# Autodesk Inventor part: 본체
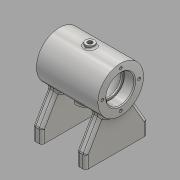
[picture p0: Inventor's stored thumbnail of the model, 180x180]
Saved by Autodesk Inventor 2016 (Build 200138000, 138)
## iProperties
Created: 2018-05
Part Number: 본체
Material: 알루미늄 6061
Document SubType Name: Modeling
Designer: Administrator
Density: 2.7 g/cm^3
Appearance: 알루미늄 - 평지
Mass: 317.695 g
Surface Area: 375.824 cm^2
Volume: 117.665 cm^3
Author: Administrator
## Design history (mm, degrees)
sketch "스케치1"
  geometry: L1 (-20, -35)-(-30, -35); L2 (-30, -35)-(-30, 35); L3 (-30, 35)-(-20, 35); L4 (-20, 35)-(-20, -35); L5 (-42, 0)-(42, 0) reference; L6 (0, -49)-(0, 49) reference; L7 (20, -35)-(30, -35); L8 (30, -35)-(30, 35); L9 (30, 35)-(20, 35); L10 (20, 35)-(20, -35); 1 further point
  constraints: 16 end point, 4 parallel, 2 horizontal, 2 perpendicular, 5 other
  dimensions: "d0" = 10 distance of L2.end L3.end; "d1" = 60 distance between parallel lines of L2 L8; "d2" = 70 distance of L9.end L7.start
extrude "돌출1" new body sketch "스케치1" distance "d3" = 15; taper "d4" = 0 deg
sketch "스케치2"
  geometry: L1 (36.295, 65)-(-44.666, 65); L2 (35, 65)-(-35, 65); L3 (-35, 65)-(-35, 91); L4 (-35, 91)-(35, 91); L5 (35, 91)-(35, 65); L6 (35, 65)-(23, 65); L7 (23, 65)-(23, 81); L8 (23, 81)-(35, 81); L9 (35, 81)-(35, 65); L10 (23, 65)-(21, 65); L11 (21, 65)-(21, 79); L12 (21, 79)-(23, 79); L13 (23, 79)-(23, 65); L14 (21, 65)-(-21, 65); L15 (-21, 65)-(-21, 86); L16 (-21, 86)-(21, 86); L17 (21, 86)-(21, 65); L18 (-21, 65)-(-23, 65); L19 (-23, 65)-(-23, 79); L20 (-23, 79)-(-21, 79); L21 (-21, 79)-(-21, 65); L22 (-23, 65)-(-35, 65); L23 (-35, 65)-(-35, 81); L24 (-35, 81)-(-23, 81); L25 (-23, 81)-(-23, 65); 2 further points
  constraints: 50 end point, 12 parallel, 7 horizontal, 6 perpendicular, 1 midpoint, 1 point on line, 1 vertical alignment
  dimensions: "d5" = 65 distance from line of point (0, 0) L1; "d6" = 70 distance of L3.end L4.end; "d7" = 26 distance of L2.end L3.end; "d8" = 12 distance of L7.end L8.end; "d9" = 16 distance of L6.end L7.end; "d10" = 2 distance of L11.end L12.end; "d11" = 14 distance of L10.end L11.end; "d12" = 42 distance of L15.end L16.end; "d13" = 21 distance of L14.end L15.end; "d14" = 2 distance of L19.end L20.end; "d15" = 14 distance of L18.end L19.end; "d16" = 12 distance of L23.end L24.end; "d17" = 16 distance of L22.end L23.end
revolve "회전1" sketch "스케치2" stored, may be unused: angle "d18" = 90 deg
sketch "스케치3"
  geometry: L1 (-30, -35)-(-30, 35) reference; L2 (-20, 35)-(-20, -35) reference; L3 (-30, -3)-(-20, -3); L4 (-20, -3)-(-20, 3); L5 (-20, 3)-(-30, 3); L6 (-30, 3)-(-30, -3); L7 (30, -35)-(30, 35) reference; L8 (20, 35)-(20, -35) reference; L9 (30, -3)-(20, -3); L10 (20, -3)-(20, 3); L11 (20, 3)-(30, 3); L12 (30, 3)-(30, -3); 4 further points
  constraints: 16 end point, 4 parallel, 4 point on line, 3 horizontal alignment, 3 midpoint, 2 horizontal, 2 perpendicular
  dimensions: "d19" = 6 distance between parallel lines of L9 L11; "d20" = 6 distance between parallel lines of L5 L3
extrude "돌출2" join sketch "스케치3" stored distance "d21" = 0; taper "d22" = 0 deg
node "작업 평면1"
sketch "스케치6"
  geometry: L1 (-15, 32)-(-15, 0) reference; L2 (-15, 0)-(-47.81, 18.943); L3 (0, 0)-(-15, 0) reference; 1 further point
  constraints: 2 end point
  dimensions: "d23" = 30 deg angle of L3 L2
feature "리브1" sketch "스케치6" dims "d24" = 1, "d25" = 10, "d26" = 0, "d27" = 0, "d28" = 1, "d29" = 1
node "작업 평면2"
sketch "스케치7"
  geometry: C1 r 5 at (0, 0); 1 further point
  constraints: 1 centre point, 1 coincident
  dimensions: "d31" = 10 diameter of C1
extrude "돌출3" join sketch "스케치7" stored distance "d32" = 15; taper "d33" = 0 deg
node "작업 평면3"
sketch "스케치8"
  geometry: L1 (-35, 26)-(35, 26) reference; L2 (-35, -26)-(-35, 26) reference; 2 further points
  constraints: 1 other
  dimensions: "d34" = 26 distance from line of L1 point (0, 0); "d35" = 35 distance from line of L2 point (0, 0)
feature "엠보싱1" sketch "스케치8" dims "d0" = 10, "d1" = 60, "d2" = 70, "d5" = 65, "d6" = 70, "d7" = 26, "d8" = 12, "d9" = 16, "d10" = 2, "d11" = 14, "d12" = 42, "d13" = 21, "d14" = 2, "d15" = 14, "d16" = 12, "d17" = 16, "d36" = 0.5, "d37" = 0
sketch "스케치9"
  geometry: L1 (-13.564, 45.276)-(-15.557, 39.801); L2 (-15.557, 39.801)-(-9.919, 37.749); L3 (-9.919, 37.749)-(0, 65); L4 (0, -18.8)-(0, 112.8) reference; L5 (-13.564, 45.276)-(-7.926, 43.224); C1 r 21 at (0, 65) reference; 1 further point
  constraints: 8 end point, 2 perpendicular, 1 parallel, 1 point on line
  dimensions: "d38" = 20 deg angle of L4 L3; "d39" = 6 distance between parallel lines of L3 L1; "d40" = 29 distance from line of L3.end L2; "d41" = 5.82629 distance between parallel lines of L2 L5
revolve "회전2" sketch "스케치9" stored, may be unused: angle "d42" = 90 deg
sketch "스케치10"
  geometry: C1 r 16 at (0, 0) reference; 2 further points
  constraints: 1 horizontal alignment
  dimensions: "d43" = 21 distance of C1.centre point (-21, 0)
hole "구멍1" sketch "스케치10" at (-21, 0) diameter "d44" = 3.242; stored, may be unused: countersink angle "d48" = 90 deg, drill point angle "d50" = 118 deg; dims "d45" = 8, "d46" = 4, "d47" = 2, "d49" = 10
hole "구멍2" diameter "d56" = 5.188; stored, may be unused: countersink angle "d60" = 90 deg, drill point angle "d62" = 118 deg; dims "d54" = 10, "d55" = 10, "d57" = 12, "d58" = 4, "d59" = 2, "d61" = 16
hole "구멍3" diameter "d65" = 5.188; stored, may be unused: countersink angle "d69" = 90 deg, drill point angle "d71" = 118 deg; dims "d63" = 10, "d64" = 10, "d66" = 12, "d67" = 4, "d68" = 2, "d70" = 16
sketch "스케치11"
  geometry: L1 (20, -35)-(30, -35) reference; L2 (30, 35)-(20, 35) reference; 5 further points
  constraints: 2 midpoint, 2 vertical alignment
  dimensions: "d72" = 40 distance of point (25, 20) point (25, -20); "d73" = 20 vertical distance of point (25, -20) point (0, 0)
hole "구멍4" sketch "스케치11" at (25, -20), (25, 20) diameter "d74" = 4.134; stored, may be unused: countersink angle "d78" = 90 deg, drill point angle "d80" = 118 deg; dims "d75" = 8, "d76" = 4, "d77" = 2, "d79" = 10
chamfer "모따기1" distance "d81" = 1; stored, may be unused: second distance "d82" = 2, angle "d83" = 45 deg
fillet "모깎기1" dims "d84" = 2
fillet "모깎기2" dims "d85" = 0.3
fillet "모깎기3" dims "d86" = 3
fillet "모깎기4" dims "d87" = 3
fillet "모깎기5" dims "d88" = 3
fillet "모깎기6" dims "d89" = 3
sketch "스케치12"
  geometry: L1 (65, 0)-(-38.669, 0); L2 (-38.669, 0)-(-38.669, 53.512); L3 (-38.669, 53.512)-(65, 53.512); L4 (65, 53.512)-(65, 0)
  constraints: 8 end point, 2 parallel, 1 horizontal, 1 perpendicular
extrude "돌출4" cut sketch "스케치12" stored distance "d90" = 0; taper "d91" = 0 deg
node "솔리드1"
mirror "대칭1"
mirror "대칭2"
pattern_circular "원형 패턴1" dims angle "d52" = 360 deg
mirror "대칭3"
mirror "대칭4"
other parameters: "d30" = 94
